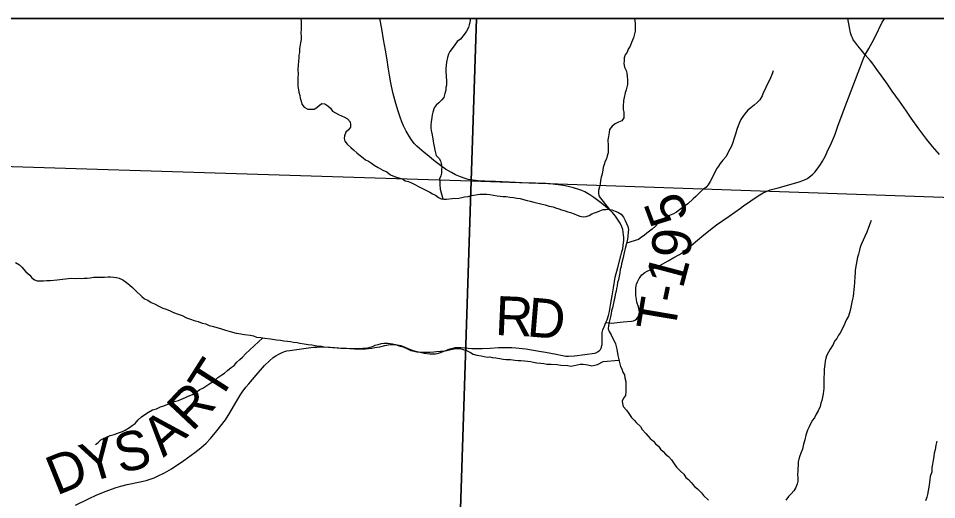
# Model space of a CAD drawing. Extents: x -3.3 to 34, y 0 to 56.8.
# Drawn here: x 0.148 to 1.485, y 34.177 to 34.877 of the extents above; entities that cross this region are included whole.
import ezdxf

# ---------------------------------------------------------------- set-up
doc = ezdxf.new("R2010")
doc.units = 0
for name, color, linetype in [('GM_X_Corporation', 7, 'Continuous'), ('GM_X_Township_Road', 7, 'Continuous'), ('GM_X_Township_Road_Text', 7, 'Continuous'), ('GT_Project_Soil_Layers', 7, 'Continuous'), ('SH_Data', 7, 'Continuous')]:
    doc.layers.add(name, color=color, linetype=linetype)

msp = doc.modelspace()

# ---------------------------------------------------------------- linework, layer by layer
at = {"layer": 'GM_X_Corporation'}
for points in [[(1.8402, 34.8771), (-3.3039, 34.8771), (-3.3039, 33.7379), (-1.9559, 33.6976), (-1.4178, 33.6828), (-1.3158, 33.6798), (-1.2647, 33.6785), (-1.2619, 33.6785), (-1.2559, 33.6783), (-1.2477, 33.6781), (-0.684, 33.6635), (0.0711, 33.6404), (0.5386, 33.6297), (1.1691, 33.6097), (1.268, 33.607), (1.3813, 33.6045), (1.3939, 33.6042), (1.4033, 33.604), (1.5156, 33.6018), (1.5452, 33.6012), (1.798, 33.5922), (1.8165, 34.1713), (1.8337, 34.7226), (1.8394, 34.8565)], [(0.815, 34.8771), (-0.2111, 34.8771), (-0.2186, 34.6726), (0.8071, 34.6408)], [(1.8405, 34.8771), (0.815, 34.8771), (0.8071, 34.6408), (1.8309, 34.6052)], [(0.8071, 34.6408), (0.7743, 33.6261), (-0.2543, 33.6541), (-0.2186, 34.6726)], [(0.8071, 34.6408), (1.8309, 34.6052), (1.8255, 34.4463), (1.797, 33.5931), (0.7743, 33.6261)]]:
    msp.add_lwpolyline(points, close=True, dxfattribs=at)
at = {"layer": 'GM_X_Township_Road'}
for points in [[(0.7844, 34.6494), (0.7786, 34.6525), (0.7699, 34.6578), (0.7605, 34.6644), (0.7528, 34.6703), (0.7454, 34.6763), (0.7387, 34.6818), (0.7318, 34.6875), (0.7279, 34.6912), (0.7244, 34.6951), (0.7204, 34.7002), (0.7168, 34.7054), (0.7125, 34.7129), (0.7089, 34.7205), (0.7062, 34.7266), (0.7038, 34.7331), (0.7008, 34.7418), (0.6973, 34.7532), (0.6932, 34.769), (0.6901, 34.7831), (0.6881, 34.7946), (0.6862, 34.8061), (0.6847, 34.8165), (0.6825, 34.8306), (0.6798, 34.8462), (0.677, 34.862), (0.6741, 34.8771)], [(1.4888, 34.6787), (1.4788, 34.6907), (1.4705, 34.7007), (1.4591, 34.7164), (1.4479, 34.7318), (1.4409, 34.7419), (1.4307, 34.7565), (1.4203, 34.7713), (1.4131, 34.7815), (1.4046, 34.7933), (1.3979, 34.8025), (1.3908, 34.8121), (1.388, 34.8157), (1.3809, 34.8242), (1.3751, 34.8311), (1.37, 34.8373), (1.3656, 34.843), (1.3635, 34.8459), (1.3621, 34.8487), (1.3609, 34.8515), (1.3596, 34.8559), (1.3579, 34.8638), (1.3556, 34.8768), (1.3555, 34.8771)], [(1.3809, 34.8242), (1.3862, 34.8334), (1.3908, 34.8419), (1.3951, 34.8501), (1.4057, 34.8715), (1.4077, 34.8747), (1.4093, 34.8769), (1.4094, 34.8771)], [(0.2311, 34.1687), (0.2502, 34.178), (0.2623, 34.1834), (0.2757, 34.189), (0.2834, 34.1921), (0.2905, 34.1945), (0.2972, 34.1964), (0.3063, 34.1986), (0.3139, 34.2001), (0.3295, 34.2035), (0.3341, 34.2047), (0.3401, 34.2066), (0.3455, 34.2085), (0.3504, 34.2107), (0.3608, 34.2157), (0.3712, 34.2214), (0.3887, 34.2334), (0.4049, 34.2454), (0.4135, 34.2522), (0.4213, 34.259), (0.4279, 34.2657), (0.4371, 34.2766), (0.4494, 34.2928), (0.456, 34.3029), (0.4647, 34.3181), (0.4717, 34.3299), (0.4737, 34.3331), (0.4791, 34.3405), (0.4833, 34.3453), (0.494, 34.3577), (0.5064, 34.372), (0.5134, 34.3788), (0.519, 34.3833), (0.5227, 34.3858), (0.526, 34.3878), (0.5311, 34.3905), (0.5354, 34.3921), (0.5387, 34.3931), (0.543, 34.3939), (0.56, 34.3961), (0.5739, 34.3978), (0.5783, 34.3983), (0.5827, 34.3987), (0.5871, 34.3989), (0.5928, 34.3988), (0.606, 34.3982), (0.6311, 34.3964), (0.6376, 34.396), (0.6535, 34.3963), (0.6627, 34.3971), (0.6671, 34.3978), (0.6743, 34.3992), (0.6814, 34.4009), (0.6865, 34.4019), (0.6897, 34.4023), (0.6929, 34.4024), (0.6971, 34.4022), (0.6997, 34.4019), (0.7024, 34.4014), (0.7048, 34.4008), (0.7074, 34.4), (0.7175, 34.3958), (0.7229, 34.3938), (0.7287, 34.3922), (0.735, 34.3908), (0.739, 34.39), (0.747, 34.3889), (0.7514, 34.3887), (0.7551, 34.389), (0.7576, 34.3894), (0.7597, 34.3899), (0.7625, 34.3908), (0.7687, 34.3931), (0.776, 34.3959), (0.7784, 34.3966), (0.7812, 34.3973), (0.7838, 34.3978), (0.788, 34.398), (0.7928, 34.398), (0.808, 34.3967), (0.8135, 34.3965), (0.823, 34.3966), (0.8349, 34.3972), (0.847, 34.3978), (0.8545, 34.3981), (0.8608, 34.3982), (0.8664, 34.398), (0.8724, 34.3977), (0.8868, 34.3959), (0.906, 34.3928), (0.9155, 34.3912), (0.9307, 34.3881), (0.94, 34.3862), (0.9448, 34.3855), (0.9488, 34.3852), (0.9576, 34.3857), (0.9725, 34.3879), (0.9866, 34.3898), (0.9885, 34.3903), (0.9899, 34.3909), (0.9913, 34.3917), (0.9941, 34.3938), (0.9953, 34.3953), (0.9962, 34.397), (0.9969, 34.3984), (0.9976, 34.4011), (0.9977, 34.4025), (0.9978, 34.4133), (0.9981, 34.4201), (0.9991, 34.4236), (1.0009, 34.4283), (1.0034, 34.4342), (1.008, 34.4338), (1.0121, 34.4336), (1.0196, 34.4343), (1.0285, 34.4354), (1.0408, 34.4366), (1.0434, 34.437), (1.0455, 34.4379), (1.048, 34.4393), (1.0504, 34.4426), (1.0515, 34.4449), (1.052, 34.4474), (1.0521, 34.4496), (1.0518, 34.4525), (1.0506, 34.457), (1.0486, 34.4639), (1.0478, 34.4681), (1.0471, 34.4739), (1.047, 34.4772), (1.0471, 34.4839), (1.0476, 34.4883), (1.048, 34.4903), (1.0492, 34.4936), (1.0506, 34.4967), (1.0518, 34.4987), (1.0532, 34.5005), (1.0557, 34.5036), (1.0598, 34.507), (1.0633, 34.5091), (1.079, 34.5158), (1.082, 34.5172), (1.094, 34.5243), (1.1023, 34.5288), (1.1105, 34.5334), (1.1162, 34.5375), (1.122, 34.542), (1.1273, 34.5463), (1.1458, 34.562), (1.16, 34.5732), (1.1643, 34.5764), (1.183, 34.589), (1.1994, 34.601), (1.2037, 34.6041), (1.2141, 34.6116), (1.2219, 34.6169), (1.2273, 34.6204), (1.2325, 34.6232), (1.2357, 34.6247), (1.2389, 34.626), (1.2425, 34.6273), (1.254, 34.6305), (1.2695, 34.6349), (1.2848, 34.6392), (1.29, 34.6409), (1.2926, 34.642), (1.2968, 34.6442), (1.2998, 34.6463), (1.3041, 34.6496), (1.3073, 34.6531), (1.311, 34.6578), (1.3157, 34.6645), (1.3187, 34.6693), (1.3224, 34.676), (1.3246, 34.6804), (1.3256, 34.6826), (1.3317, 34.6959), (1.3361, 34.7061), (1.337, 34.7084), (1.3411, 34.7204), (1.3501, 34.7451), (1.3604, 34.7715), (1.3767, 34.8148), (1.3785, 34.8188), (1.3809, 34.8242)], [(1.0107, 34.4627), (1.0123, 34.4733), (1.0142, 34.485), (1.017, 34.5003), (1.0205, 34.5147), (1.025, 34.5313), (1.0267, 34.5374), (1.0278, 34.5418), (1.0287, 34.5468), (1.0291, 34.5503), (1.0293, 34.5536), (1.0292, 34.5576), (1.029, 34.5618), (1.0286, 34.5657), (1.0278, 34.5697), (1.0264, 34.5737), (1.0239, 34.5788), (1.0214, 34.5832), (1.0172, 34.589), (1.0127, 34.5945), (1.0082, 34.599), (0.9974, 34.6074), (0.9858, 34.6162), (0.9799, 34.6204), (0.9728, 34.6245), (0.9684, 34.6264), (0.9639, 34.6282), (0.9564, 34.6306), (0.9503, 34.6319), (0.944, 34.6333), (0.9379, 34.6343), (0.9293, 34.6354), (0.9221, 34.6361), (0.9159, 34.6365), (0.901, 34.6372), (0.8811, 34.6379), (0.8625, 34.6387), (0.8426, 34.6395), (0.8273, 34.6401), (0.8175, 34.6407), (0.8094, 34.6416), (0.8029, 34.6426), (0.7983, 34.6438), (0.7916, 34.6462), (0.7844, 34.6494)], [(1.0034, 34.4342), (1.005, 34.4384), (1.0069, 34.4447), (1.0085, 34.4505), (1.0097, 34.4566), (1.0107, 34.4627)]]:
    msp.add_lwpolyline(points, dxfattribs=at)
at = {"layer": 'GT_Project_Soil_Layers'}
for points in [[(0.559, 34.8771), (0.5591, 34.8769), (0.5595, 34.8716), (0.5597, 34.8613), (0.5594, 34.8557), (0.5598, 34.8507), (0.5595, 34.8465), (0.5588, 34.8416), (0.5574, 34.8325), (0.5571, 34.8272), (0.5564, 34.8234), (0.5561, 34.8196), (0.5557, 34.815), (0.5551, 34.8032), (0.5553, 34.7953), (0.5549, 34.7915), (0.5551, 34.7778), (0.5556, 34.7732), (0.5564, 34.7695), (0.5576, 34.7649), (0.5584, 34.7608), (0.5596, 34.7566), (0.5608, 34.7521), (0.5642, 34.7479), (0.5696, 34.745), (0.5741, 34.7447), (0.5787, 34.7451), (0.5824, 34.7474), (0.5862, 34.7509), (0.5899, 34.7532), (0.5941, 34.7529), (0.5983, 34.7499), (0.6022, 34.7462), (0.6053, 34.742), (0.6095, 34.7398), (0.614, 34.7372), (0.6182, 34.735), (0.6228, 34.7332), (0.627, 34.731), (0.6309, 34.7265), (0.6313, 34.7227), (0.6314, 34.7189), (0.6284, 34.7147), (0.6246, 34.7112), (0.6228, 34.7062), (0.6221, 34.7024), (0.6233, 34.6983), (0.6268, 34.6941), (0.6318, 34.6893), (0.636, 34.6855), (0.6414, 34.6811), (0.6456, 34.6773), (0.6498, 34.674), (0.6536, 34.6714), (0.6578, 34.6691), (0.662, 34.6665), (0.6662, 34.6636), (0.672, 34.6602), (0.6785, 34.6562), (0.6842, 34.6536), (0.6899, 34.6495), (0.6957, 34.6469), (0.7002, 34.6454), (0.7071, 34.6433), (0.7113, 34.6407), (0.7158, 34.6396), (0.7204, 34.6378), (0.725, 34.6355), (0.7307, 34.6326), (0.7346, 34.6304), (0.7384, 34.6285), (0.7422, 34.6263), (0.7468, 34.6241), (0.751, 34.6215), (0.7552, 34.6196), (0.7598, 34.6163), (0.7636, 34.6144), (0.7674, 34.6141), (0.7712, 34.6138), (0.7795, 34.6147), (0.7894, 34.6156), (0.7935, 34.6164), (0.7973, 34.6172)], [(0.8055, 34.8771), (0.8056, 34.8738), (0.8045, 34.8678), (0.8031, 34.8636), (0.8005, 34.8586), (0.7971, 34.8536), (0.7915, 34.8467), (0.787, 34.8432), (0.7833, 34.8386), (0.7796, 34.8333), (0.7762, 34.829), (0.774, 34.8248), (0.7726, 34.8199), (0.7715, 34.8134), (0.7701, 34.8043), (0.7702, 34.8005), (0.771, 34.7925), (0.7715, 34.7861), (0.7712, 34.78), (0.7705, 34.7762), (0.7702, 34.7724), (0.7687, 34.7675), (0.7673, 34.7621), (0.7643, 34.7583), (0.7602, 34.7541), (0.7564, 34.7506), (0.7535, 34.7468), (0.7513, 34.7403), (0.7502, 34.7365), (0.7499, 34.7327), (0.7488, 34.7266), (0.7485, 34.7216), (0.7485, 34.7178), (0.749, 34.7137), (0.7502, 34.7076), (0.7518, 34.6985), (0.7523, 34.6947), (0.7531, 34.6906), (0.7543, 34.6853), (0.7551, 34.6815), (0.7563, 34.6777), (0.7605, 34.6732), (0.7625, 34.6695), (0.7636, 34.6657), (0.7645, 34.6611), (0.7641, 34.657), (0.7638, 34.652), (0.7631, 34.6478), (0.7613, 34.6433), (0.7617, 34.6387), (0.7618, 34.6353), (0.7623, 34.6285), (0.7661, 34.6142)], [(1.0449, 34.8771), (1.0457, 34.8703), (1.0458, 34.8586), (1.0451, 34.8547), (1.0433, 34.8487), (1.0407, 34.8418), (1.0385, 34.8364), (1.0359, 34.8322), (1.0345, 34.828), (1.0315, 34.8242), (1.03, 34.8196), (1.0297, 34.8154), (1.0294, 34.8113), (1.0306, 34.806), (1.0326, 34.8014), (1.0337, 34.7973), (1.0342, 34.7927), (1.0346, 34.7871), (1.0347, 34.7806), (1.0326, 34.773), (1.0315, 34.7688), (1.0301, 34.7619), (1.029, 34.7574), (1.0283, 34.7486), (1.0284, 34.7445), (1.0292, 34.7403), (1.0296, 34.7365), (1.0293, 34.7323), (1.0263, 34.7281), (1.0218, 34.7258), (1.0169, 34.7234), (1.0124, 34.72), (1.0087, 34.7154), (1.008, 34.7108), (1.0073, 34.7051), (1.0062, 34.7005), (1.0064, 34.6914), (1.0068, 34.6857), (1.0065, 34.6815), (1.0054, 34.677), (1.0043, 34.6728), (1.0025, 34.669), (1.0007, 34.6644), (0.9992, 34.6602), (0.9989, 34.6564), (0.9978, 34.6503), (0.9964, 34.6457), (0.9957, 34.6412), (0.995, 34.6358), (0.9939, 34.6317), (0.9928, 34.6267), (0.9925, 34.6222), (0.9937, 34.6176), (1.0088, 34.599)], [(1.2468, 34.8006), (1.2453, 34.7964), (1.2428, 34.7903), (1.2406, 34.7853), (1.2376, 34.7796), (1.2347, 34.7731), (1.2321, 34.7685), (1.2306, 34.7643), (1.2273, 34.7586), (1.2235, 34.7547), (1.2194, 34.7509), (1.2145, 34.747), (1.21, 34.7435), (1.2056, 34.7382), (1.2026, 34.7343), (1.2, 34.7297), (1.1978, 34.7255), (1.1959, 34.7206), (1.1941, 34.7152), (1.1919, 34.7084), (1.1897, 34.7011), (1.1883, 34.6966), (1.1861, 34.6912), (1.1839, 34.6866), (1.1813, 34.6824), (1.1783, 34.6759), (1.1735, 34.6706), (1.1697, 34.666), (1.1671, 34.6621), (1.1645, 34.6579), (1.1623, 34.6537), (1.1549, 34.6396), (1.152, 34.635), (1.1486, 34.6311), (1.1441, 34.6273), (1.1389, 34.6226), (1.1344, 34.618), (1.1302, 34.6146), (1.1224, 34.6069), (1.1145, 34.6014), (1.1107, 34.5983), (1.1059, 34.5949), (1.1006, 34.5921), (1.0957, 34.5902), (1.0919, 34.5882), (1.0882, 34.5859), (1.0833, 34.5824), (1.0795, 34.5789), (1.0754, 34.5747), (1.0705, 34.5705), (1.0668, 34.5674), (1.0627, 34.5643), (1.0589, 34.5612), (1.0552, 34.5585), (1.051, 34.5554), (1.0334, 34.55)], [(0.7973, 34.6172), (0.803, 34.618), (0.8071, 34.6192), (0.8109, 34.6196), (0.8162, 34.6209), (0.82, 34.6213), (0.8302, 34.6214), (0.8344, 34.6207), (0.845, 34.619), (0.8496, 34.6183), (0.8534, 34.618), (0.858, 34.6176), (0.8637, 34.617), (0.8686, 34.6163), (0.8739, 34.6156), (0.8785, 34.6149), (0.8834, 34.6134), (0.8887, 34.612), (0.8933, 34.6109), (0.8986, 34.6095), (0.9024, 34.6088), (0.9066, 34.6077), (0.9104, 34.6066), (0.915, 34.6055), (0.9207, 34.6037), (0.9264, 34.6026), (0.9302, 34.6012), (0.9348, 34.5997), (0.9386, 34.5986), (0.9439, 34.5968), (0.9477, 34.5953), (0.9519, 34.5946), (0.9569, 34.5928), (0.9615, 34.5906), (0.9656, 34.5891), (0.9702, 34.5884), (0.9747, 34.5889), (0.9789, 34.5901), (0.983, 34.5924), (0.9868, 34.594), (0.991, 34.5956), (0.9947, 34.5971), (0.9993, 34.5987), (1.0038, 34.5988), (1.0076, 34.5992), (1.0122, 34.5985), (1.0167, 34.5967), (1.0209, 34.5948), (1.0255, 34.5919), (1.029, 34.5877), (1.0313, 34.5828), (1.0333, 34.5787), (1.0352, 34.5742), (1.0361, 34.57), (1.0357, 34.5662), (1.0354, 34.5597), (1.0347, 34.5556), (1.0333, 34.5495), (1.0315, 34.5422), (1.0304, 34.5384), (1.0293, 34.5338), (1.0283, 34.5289), (1.0261, 34.5198), (1.0254, 34.516), (1.0243, 34.5114), (1.0236, 34.5068), (1.0226, 34.5019), (1.0215, 34.4965), (1.0204, 34.4927), (1.0197, 34.4878), (1.0186, 34.484), (1.0183, 34.4798), (1.0169, 34.4752), (1.0162, 34.471), (1.0154, 34.4672), (1.0129, 34.4558), (1.0115, 34.4516), (1.0112, 34.4474), (1.0101, 34.4429), (1.009, 34.4387), (1.0083, 34.4349), (1.0072, 34.4299), (1.0065, 34.425), (1.0081, 34.4212), (1.0108, 34.4167), (1.0124, 34.4129), (1.0155, 34.4076), (1.0171, 34.4035), (1.0183, 34.3997), (1.0191, 34.3955), (1.0207, 34.3865), (1.0215, 34.3823), (1.0227, 34.3781), (1.0247, 34.3706), (1.0263, 34.3668), (1.0282, 34.3623), (1.0302, 34.3581), (1.031, 34.354), (1.0322, 34.3487), (1.0324, 34.3339), (1.0317, 34.3282)], [(1.3893, 34.5828), (1.3878, 34.579), (1.3856, 34.5725), (1.3831, 34.566), (1.3801, 34.5595), (1.3753, 34.5488), (1.3735, 34.5443), (1.3724, 34.5397), (1.371, 34.534), (1.3695, 34.5294), (1.3678, 34.5188), (1.3664, 34.5108), (1.366, 34.5066), (1.3657, 34.5013), (1.3651, 34.4925), (1.3648, 34.4868), (1.3645, 34.4823), (1.3638, 34.4777), (1.3631, 34.4724), (1.3624, 34.4686), (1.3613, 34.464), (1.3606, 34.4591), (1.3588, 34.4518), (1.3566, 34.4438), (1.3537, 34.4389), (1.3518, 34.4343), (1.3504, 34.4305), (1.3478, 34.4263), (1.3448, 34.4201), (1.3419, 34.4159), (1.3396, 34.411), (1.3359, 34.4071), (1.3341, 34.4025), (1.3296, 34.3956), (1.3274, 34.3914), (1.3244, 34.3861), (1.3237, 34.3823), (1.3226, 34.3781), (1.3219, 34.3735), (1.3213, 34.3667), (1.321, 34.3602), (1.3207, 34.3545), (1.3208, 34.3496), (1.3205, 34.3439), (1.3205, 34.3382), (1.3202, 34.3344), (1.3195, 34.3306), (1.3188, 34.3257), (1.3177, 34.3207), (1.3163, 34.3169), (1.3152, 34.3123), (1.3122, 34.3058), (1.3093, 34.3009), (1.3071, 34.2955), (1.3037, 34.2917), (1.2993, 34.2825), (1.2967, 34.2779), (1.2945, 34.2703), (1.2931, 34.2638), (1.2909, 34.2573), (1.2895, 34.2501), (1.2869, 34.2444), (1.2858, 34.2402), (1.2844, 34.2356), (1.2833, 34.2314), (1.283, 34.2261), (1.2827, 34.2219), (1.2827, 34.2174), (1.2824, 34.2136), (1.2829, 34.2079), (1.2825, 34.2033), (1.2818, 34.1995), (1.2796, 34.1942), (1.2767, 34.1892), (1.2729, 34.1853), (1.2692, 34.1811), (1.2655, 34.1757)], [(0.1441, 34.5219), (0.1495, 34.5182), (0.1533, 34.5149), (0.1591, 34.5081), (0.1649, 34.5033), (0.1676, 34.4995), (0.1714, 34.4965), (0.1756, 34.4951), (0.1847, 34.4952), (0.1896, 34.4956), (0.1945, 34.4957), (0.2044, 34.4966), (0.2082, 34.497), (0.2203, 34.4987), (0.2256, 34.4988), (0.2317, 34.4985), (0.2358, 34.4989), (0.2396, 34.4986), (0.2438, 34.499), (0.248, 34.4991), (0.2525, 34.4995), (0.2574, 34.5004), (0.2733, 34.5006), (0.2786, 34.5011), (0.2824, 34.5007), (0.287, 34.5004), (0.2908, 34.4997), (0.295, 34.499), (0.3003, 34.4964), (0.3053, 34.4927), (0.3103, 34.489), (0.3141, 34.4852), (0.3187, 34.4811), (0.3279, 34.4721), (0.3318, 34.4688), (0.3364, 34.4669), (0.3413, 34.4636), (0.3463, 34.4614), (0.3524, 34.458), (0.3585, 34.4555), (0.3631, 34.454), (0.3688, 34.4514), (0.3741, 34.4489), (0.3806, 34.4467), (0.3863, 34.4445), (0.3928, 34.4412), (0.3985, 34.4393), (0.4039, 34.4375), (0.4096, 34.4361), (0.4157, 34.4335), (0.421, 34.4324), (0.426, 34.4302), (0.432, 34.4288), (0.437, 34.427), (0.4423, 34.4259), (0.4496, 34.4233), (0.4564, 34.4212), (0.4652, 34.419), (0.469, 34.4183), (0.4773, 34.4169), (0.4853, 34.4159), (0.4902, 34.4148), (0.4948, 34.4133), (0.5009, 34.4127), (0.507, 34.4116), (0.5153, 34.4106), (0.5237, 34.4092)], [(0.2603, 34.2571), (0.2641, 34.2598), (0.2682, 34.2636), (0.272, 34.2656), (0.2761, 34.2676), (0.2818, 34.2699), (0.2874, 34.2715), (0.2916, 34.2731), (0.2954, 34.2743), (0.2995, 34.2759), (0.3037, 34.2778), (0.3097, 34.2817), (0.3138, 34.2844), (0.3179, 34.2875), (0.3224, 34.2929), (0.3273, 34.2971), (0.3337, 34.3014), (0.3374, 34.3041), (0.3434, 34.3072), (0.3491, 34.3088), (0.3548, 34.3116), (0.3585, 34.3127), (0.3646, 34.3151), (0.371, 34.3175), (0.3755, 34.3194), (0.3812, 34.321), (0.3865, 34.3234), (0.3902, 34.3246), (0.3951, 34.3273), (0.4015, 34.3297), (0.4068, 34.3332), (0.4124, 34.3367), (0.4166, 34.339), (0.4282, 34.3467), (0.4335, 34.3499), (0.4384, 34.3545), (0.444, 34.3584), (0.4481, 34.3607), (0.4526, 34.3645), (0.4579, 34.3688), (0.462, 34.3719), (0.4661, 34.3765), (0.4706, 34.3804), (0.4744, 34.3842), (0.4788, 34.3888), (0.504, 34.4121)], [(0.5237, 34.4092), (0.5298, 34.4089), (0.5343, 34.4078), (0.5396, 34.4071), (0.5442, 34.4068), (0.5488, 34.4057), (0.5537, 34.4054), (0.5579, 34.4043), (0.564, 34.4033), (0.57, 34.4026), (0.5754, 34.4019), (0.5803, 34.4009), (0.5856, 34.4002), (0.5894, 34.3999), (0.5932, 34.3991), (0.6019, 34.3985), (0.6084, 34.3978), (0.6122, 34.3975), (0.6175, 34.3972), (0.6217, 34.3973), (0.6255, 34.3969), (0.63, 34.3966), (0.6497, 34.3969), (0.6539, 34.3973), (0.6588, 34.3982), (0.6637, 34.3997), (0.6675, 34.4013), (0.6717, 34.4025), (0.6766, 34.4041), (0.6803, 34.4045), (0.686, 34.4042), (0.6929, 34.4036), (0.6971, 34.4025), (0.702, 34.4007), (0.7081, 34.3988), (0.7134, 34.3966), (0.7195, 34.3937), (0.7241, 34.3926), (0.7283, 34.3915), (0.7332, 34.3912), (0.7469, 34.3914), (0.7529, 34.3919), (0.7567, 34.3923), (0.7624, 34.3928), (0.767, 34.3928), (0.7719, 34.3937), (0.7757, 34.3948), (0.7802, 34.3957), (0.7844, 34.3965), (0.79, 34.3966), (0.7942, 34.3955), (0.8003, 34.3937), (0.806, 34.3907), (0.8102, 34.3885), (0.8156, 34.3867), (0.8216, 34.386), (0.8262, 34.3849), (0.8304, 34.3842), (0.8342, 34.3843), (0.838, 34.3836), (0.8429, 34.3829), (0.849, 34.3818), (0.8536, 34.3811), (0.8581, 34.3808), (0.8646, 34.3805), (0.8706, 34.3798), (0.8756, 34.3791), (0.8794, 34.3792), (0.8847, 34.3785), (0.8892, 34.3782), (0.8934, 34.3775), (0.898, 34.3768), (0.9029, 34.3757), (0.9082, 34.375), (0.9128, 34.3747), (0.9174, 34.374), (0.9238, 34.3737), (0.9325, 34.3731), (0.9379, 34.3724), (0.9477, 34.3718), (0.9523, 34.3711), (0.9572, 34.3719), (0.9617, 34.3727), (0.9659, 34.3736), (0.9704, 34.374), (0.9742, 34.3733), (0.9792, 34.3722), (0.983, 34.3715), (0.9872, 34.3723), (0.9909, 34.3735), (0.9992, 34.3778), (1.0223, 34.3794)], [(1.0317, 34.3282), (1.0288, 34.3243), (1.0269, 34.3201), (1.0273, 34.3163), (1.0285, 34.3122), (1.0332, 34.3069), (1.0366, 34.302), (1.0405, 34.296), (1.0447, 34.2923), (1.0478, 34.2885), (1.0536, 34.2829), (1.0559, 34.2788), (1.0617, 34.2728), (1.0678, 34.2656), (1.0728, 34.2619), (1.0755, 34.2578), (1.0801, 34.2544), (1.0828, 34.2503), (1.0867, 34.2465), (1.0901, 34.2428), (1.0947, 34.2394), (1.0986, 34.2346), (1.1017, 34.2304), (1.1063, 34.2237), (1.1117, 34.218), (1.1167, 34.2135), (1.1198, 34.2087), (1.1236, 34.2061), (1.1275, 34.2016), (1.1325, 34.1955), (1.1367, 34.1922), (1.1425, 34.1866), (1.1456, 34.1828), (1.1525, 34.1757)], [(1.485, 34.2615), (1.4836, 34.2558), (1.4825, 34.249), (1.4814, 34.2444), (1.4807, 34.2394), (1.4797, 34.2341), (1.479, 34.2284), (1.4779, 34.2235), (1.4776, 34.217), (1.4754, 34.2105), (1.4751, 34.2052), (1.4734, 34.1949), (1.4727, 34.1892), (1.4716, 34.1843), (1.4706, 34.1801), (1.4687, 34.1747)]]:
    msp.add_lwpolyline(points, dxfattribs=at)
at = {"layer": 'SH_Data'}
msp.add_line((-3.3039, 34.8771), (3.4961, 34.8771), dxfattribs=at)

# ---------------------------------------------------------------- texts
at = {"layer": 'GM_X_Township_Road_Text'}
for s, rotation, p in [('5', 110.4777, (1.1249, 34.5885)), ('9', 85.5521, (1.1259, 34.5271)), ('1', 75.1913, (1.1151, 34.4823)), ('-', 78.0884, (1.1104, 34.4602)), ('R', 357.5247, (0.8413, 34.4164)), ('D', 355.1641, (0.8873, 34.4144)), ('T', 80.4285, (1.1035, 34.4189)), ('T', 57.4694, (0.4401, 34.3175)), ('R', 46.7898, (0.4011, 34.2743)), ('A', 41.3364, (0.3593, 34.2372)), ('S', 13.7193, (0.2958, 34.2144)), ('Y', 16.5293, (0.2486, 34.2004)), ('D', 21.8941, (0.2035, 34.1822))]:
    msp.add_text(s, height=0.0568, rotation=rotation, dxfattribs=at).set_placement(p)

doc.saveas('drawing.dxf')
